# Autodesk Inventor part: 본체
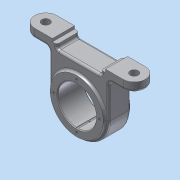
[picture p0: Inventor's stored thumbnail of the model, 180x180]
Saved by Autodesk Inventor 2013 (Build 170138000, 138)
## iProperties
Created: 2019-05
Part Number: 본체
Material: 알루미늄 6061
Document SubType Name: Modeling
Designer: dgall
Density: 2.71 g/cm^3
Mass: 456.709 g
Surface Area: 318.663 cm^2
Volume: 168.527 cm^3
Author: dgall
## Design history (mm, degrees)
sketch "스케치1"
  geometry: C1 r 40 at (0, 0); C2 r 36 at (0, 0); C3 r 26 at (0, 0); 1 further point
  constraints: 3 centre point, 3 coincident
  dimensions: "d0" = 40 radius of C1; "d1" = 36 radius of C2; "d2" = 26 radius of C3
extrude "돌출1" new body sketch "스케치1" stored distance "d3" = 36; taper "d4" = 0 deg
extrude "돌출2" join sketch "스케치1" stored distance "d5" = 30; taper "d6" = 0 deg
sketch "스케치2"
  geometry: L1 (40, 0)-(40, 48); L2 (40, 48)-(75, 48); L3 (75, 48)-(75, 60); L4 (75, 60)-(36, 60); L5 (36, 60)-(36, 56); L6 (36, 56)-(30, 56); L7 (30, 56)-(30, 50); L8 (30, 50)-(-30, 50); L9 (-30, 50)-(-30, 56); L10 (-30, 56)-(-36, 56); L11 (-36, 56)-(-36, 60); L12 (-36, 60)-(-75, 60); L13 (-75, 60)-(-75, 48); L14 (-75, 48)-(-40, 48); L15 (-40, 48)-(-40, 0); C1 r 26 at (0, 0) reference; A1 r 40 centre (0, 0) between (40, 0) and (-40, 0) reference; 2 further points
  constraints: 30 end point, 8 vertical, 7 horizontal, 6 equal length, 2 point on circle, 1 midpoint, 1 tangent, 1 vertical alignment
  dimensions: "d7" = 4 distance of L4.end L5.end; "d8" = 10 distance between parallel lines of L8 L4; "d9" = 12 distance of L2.end L3.end; "d10" = 60 distance from line of point (0, 0) L4; "d11" = 60 distance of L7.end L8.end; "d12" = 72 distance between parallel lines of L11 L5; "d13" = 150 distance between parallel lines of L13 L3
extrude "돌출3" join sketch "스케치2" stored distance "d14" = 30; taper "d15" = 0 deg
fillet "모깎기1" dims "d16" = 15
fillet "모깎기2" dims "d17" = 6
fillet "모깎기3" dims "d18" = 3
sketch "스케치3"
  geometry: C1 r 26 at (0, 0) reference; 1 further point
  constraints: 1 vertical alignment
  dimensions: "d19" = 31 distance of C1.centre point (0, 31)
hole "구멍1" sketch "스케치3" at (0, 31) diameter "d20" = 3.242; stored, may be unused: countersink angle "d24" = 90 deg, drill point angle "d26" = 118 deg; dims "d21" = 6, "d22" = 4, "d23" = 2, "d25" = 8
sketch "스케치4"
  geometry: C1 r 9 at (14, 12); A1 r 12 centre (14, 12) between (14, 0) and (14, 24) reference; 1 further point
  constraints: 1 centre point, 1 coincident
  dimensions: "d30" = 9 radius of C1
extrude "돌출4" join sketch "스케치4" distance "d31" = 3; taper "d32" = 0 deg
hole "구멍2" diameter "d35" = 11; stored, may be unused: countersink angle "d39" = 90 deg, drill point angle "d41" = 118 deg; dims "d33" = 10, "d34" = 10, "d36" = 11, "d37" = 4, "d38" = 2, "d40" = 8
fillet "모깎기4" dims "d42" = 3
node "작업 평면1"
sketch "스케치5"
  geometry: C1 r 3.5 at (0, 0); 1 further point
  constraints: 1 centre point, 1 coincident
  dimensions: "d43" = 3.5 radius of C1
extrude "돌출5" cut sketch "스케치5" distance "d44" = 1; taper "d45" = 0 deg
hole "구멍3" diameter "d48" = 4.917; stored, may be unused: countersink angle "d52" = 90 deg, drill point angle "d54" = 118 deg; dims "d49" = 7, "d50" = 4, "d51" = 2, "d53" = 9, "d68" = 10, "d69" = 10
sketch "스케치6"
  geometry: C1 r 3.5 at (0, 0) reference; C2 r 1 at (0, 0)
  constraints: 1 centre point, 1 coincident
  dimensions: "d55" = 1 radius of C2
extrude "돌출6" cut sketch "스케치6" stored distance "d56" = 1; taper "d57" = 0 deg
fillet "모깎기5" dims "d58" = 3
sketch "스케치7"
  geometry: C1 r 1.621 at (0, 31) reference; C2 r 1.5 at (0, 26); 1 further point
  constraints: 2 vertical alignment, 1 centre point, 1 other
  dimensions: "d59" = 1.5 radius of C2
extrude "돌출7" cut sketch "스케치7" stored distance "d60" = 1; taper "d61" = 0 deg
sketch "스케치8"
  geometry: L1 (-36, -60)-(-60, -60) reference; L2 (-60, -60)-(-60, -51) reference; L3 (-60, -51)-(-46, -51) reference; L4 (-37, -42)-(-37, -12.329) reference; L5 (37, -12.329)-(37, -42) reference; L6 (46, -51)-(60, -51) reference; L7 (60, -51)-(60, -60) reference; L8 (60, -60)-(36, -60) reference; L9 (36, -60)-(36, -56) reference; L10 (36, -56)-(33, -56) reference; L11 (33, -56)-(33, -53) reference; L12 (27, -47)-(-27, -47) reference; L13 (-33, -53)-(-33, -56) reference; L14 (-33, -56)-(-36, -56) reference; L15 (-36, -56)-(-36, -60) reference; L16 (-27, -50)-(27, -50) reference; C1 r 1.621 at (31, 0) reference; C2 r 1.621 at (0, -31) reference; C3 r 1.621 at (-31, 0) reference; C4 r 1.621 at (0, 31) reference; A1 r 39 centre (0, 0) between (-37, -12.329) and (37, -12.329) reference; A2 r 1.5 centre (0, 26) between (1.499, 25.957) and (-1.499, 25.957) reference; A3 r 26 centre (0, 0) between (-1.499, 25.957) and (1.499, 25.957) reference; A4 r 9 centre (-46, -42) between (-46, -51) and (-37, -42) reference; A5 r 37.607 centre (0, 0) between (37.607, 0) and (-37.607, 0) reference; A6 r 9 centre (46, -42) between (37, -42) and (46, -51) reference; A7 r 6 centre (27, -53) between (33, -53) and (27, -47) reference; A8 r 6 centre (-27, -53) between (-27, -47) and (-33, -53) reference; A9 r 39 centre (0, 0) between (-37, -12.329) and (37, -12.329) reference; 1 further point
  constraints: 1 vertical alignment, 3 other
  dimensions: "d62" = 7 distance from line of L16 point (0, -43)
feature "엠보싱1" sketch "스케치8" dims "d63" = 0.5, "d64" = 0
chamfer "모따기1" distance "d65" = 1; stored, may be unused: second distance "d66" = 2, angle "d67" = 45 deg
node "솔리드1"
pattern_circular "원형 패턴1" dims angle "d28" = 360 deg
mirror "대칭1"
mirror "대칭2"
mirror "대칭3"
node "절단 모서리 투영1"
node "절단 모서리 투영2"
